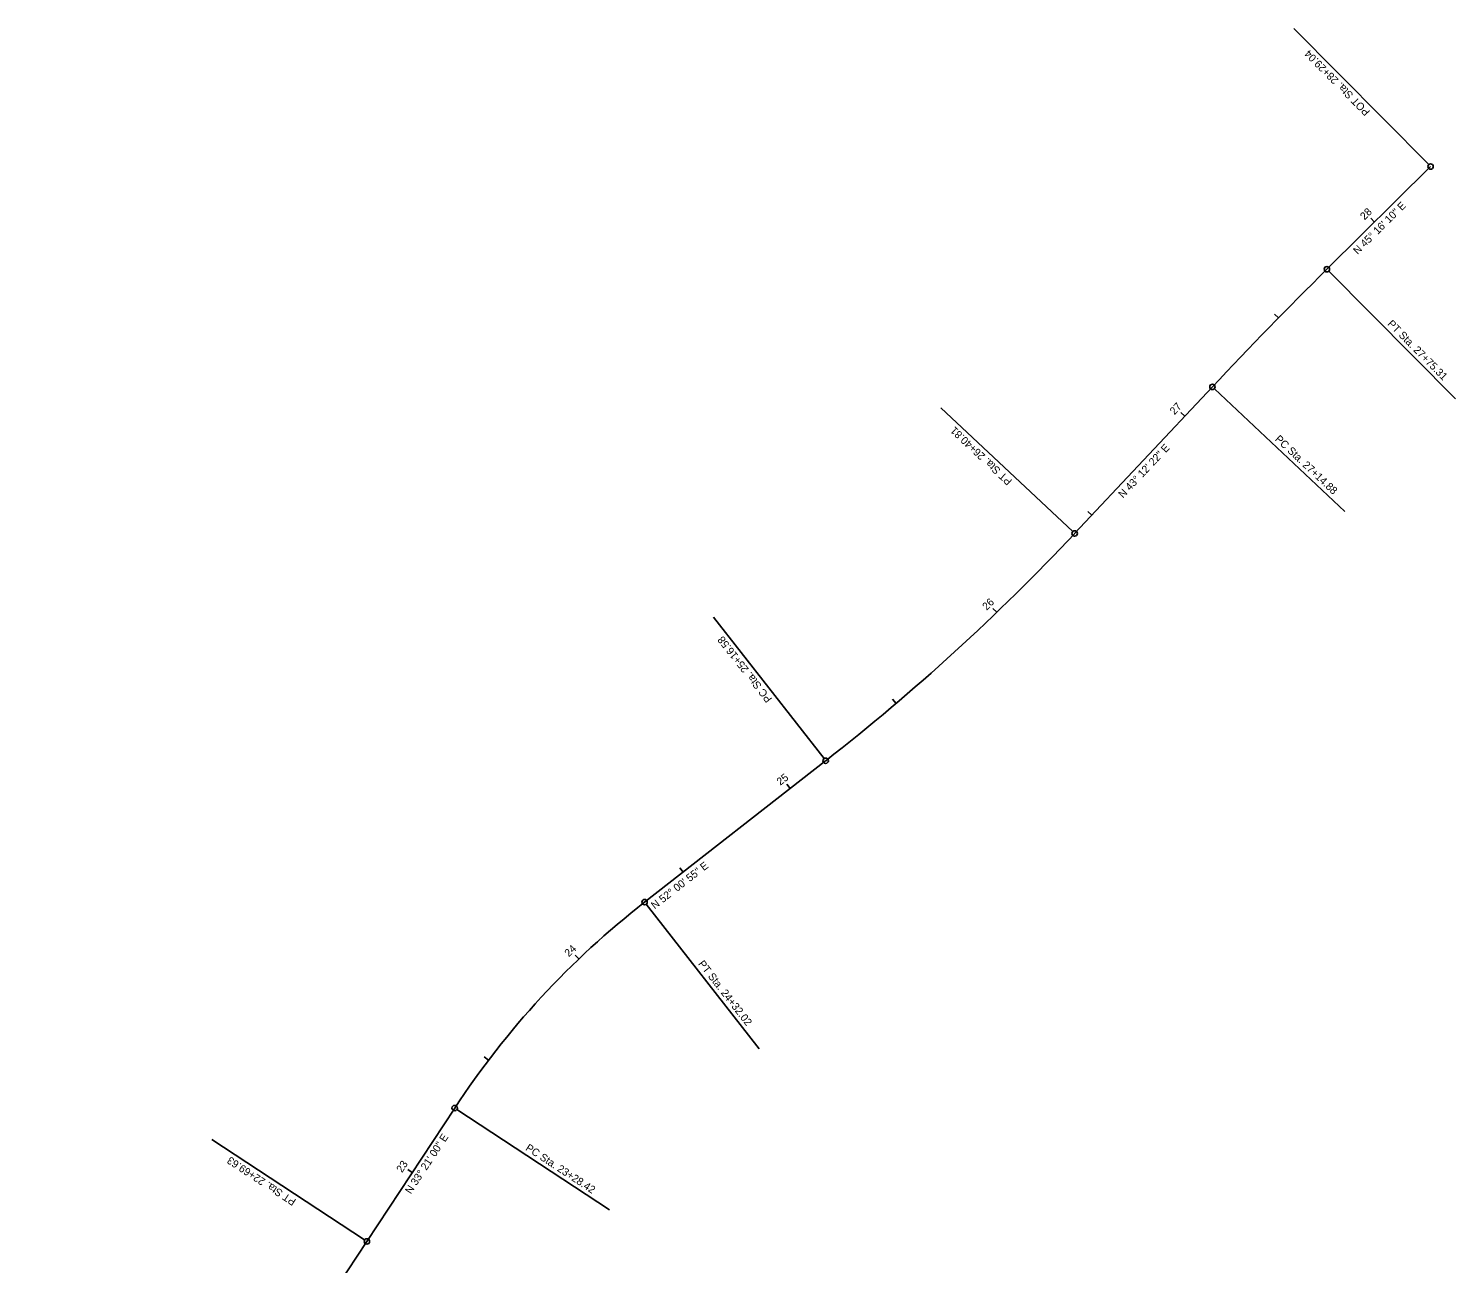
# Model space of a CAD drawing. Extents: x 1869622 to 1870464, y 422115 to 423925.
# Drawn here: x 1869717 to 1870243, y 423471 to 423925 of the extents above; entities that cross this region are included whole.
import ezdxf

# ---------------------------------------------------------------- set-up
doc = ezdxf.new("R2010")
doc.units = 0
doc.layers.add('GE_P_CL_20', color=7, linetype='Continuous')

msp = doc.modelspace()

# ---------------------------------------------------------------- linework, layer by layer
at = {"layer": 'GE_P_CL_20'}
for p, q in [((1870232.93, 423875.26), (1870183.3, 423925.36)), ((1870195.46, 423836.74), (1870233.63, 423874.55)), ((1870213, 423854.11), (1870211.59, 423855.53)), ((1870196.16, 423836.03), (1870242.78, 423788.97)), ((1870177.61, 423818.79), (1870176.18, 423820.19)), ((1870102.59, 423739.46), (1870153.3, 423793.44)), ((1870154.03, 423792.76), (1870202.11, 423747.6)), ((1870101.87, 423740.14), (1870053.31, 423785.75)), ((1870143.12, 423782.6), (1870141.66, 423783.97)), ((1870108.88, 423746.15), (1870107.43, 423747.52)), ((1870073.91, 423710.43), (1870072.53, 423711.87)), ((1870010.32, 423656.57), (1869969.68, 423708.61)), ((1870036.84, 423676.89), (1870035.54, 423678.42)), ((1869944.28, 423603.74), (1870010.93, 423655.79)), ((1869997.86, 423645.58), (1869996.63, 423647.16)), ((1869958.45, 423614.81), (1869957.22, 423616.38)), ((1869944.89, 423602.95), (1869986.44, 423549.75)), ((1869920.08, 423582.8), (1869918.69, 423584.24)), ((1869886.82, 423545.53), (1869885.23, 423546.74)), ((1869842.04, 423478.81), (1869874.36, 423527.92)), ((1869875.19, 423527.37), (1869931.3, 423490.45)), ((1869841.2, 423479.36), (1869784.93, 423516.4)), ((1869858.73, 423504.18), (1869857.06, 423505.28))]:
    msp.add_line(p, q, dxfattribs=at)
for centre in [(1870233.63, 423874.55), (1870195.46, 423836.74), (1870153.3, 423793.44), (1870102.59, 423739.46), (1870010.93, 423655.79), (1869944.28, 423603.74), (1869874.36, 423527.92), (1869842.04, 423478.81)]:
    msp.add_circle(centre, 1, dxfattribs=at)
for centre, radius, start, end in [((1871376.39, 422644.65), 1678, 134.73056, 136.79402), ((1869513.65, 424292.63), 808, 307.98484, 316.79402), ((1870139.99, 423353.1), 318, 127.9848, 146.6499), ((1868467.92, 424383.15), 1645, 319.42979, 326.64993)]:
    msp.add_arc(centre, radius, start, end, dxfattribs=at)

# ---------------------------------------------------------------- texts
for s, rotation, p in [('POT Sta. 28+29.04', 134.7306, (1870211.52, 423894.88)), ('N 45%%d 16\' 10" E', 44.7306, (1870206.75, 423842.01)), ('28', 44.7306, (1870209.32, 423854.69)), ('PT Sta. 27+75.31', 314.7306, (1870217.57, 423816.41)), ('27', 46.794, (1870139.34, 423782.96)), ('PT Sta. 26+40.81', 136.794, (1870079.77, 423758.97)), ('PC Sta. 27+14.88', 316.794, (1870176.13, 423773.92)), ('N 43%%d 12\' 22" E', 46.794, (1870120.41, 423752.29)), ('26', 43.9, (1870070.2, 423711.01)), ('PC Sta. 25+16.58', 127.9848, (1869991.36, 423678.57)), ('25', 37.9848, (1869994.23, 423646.55)), ('N 52%%d 00\' 55" E', 37.9848, (1869948.01, 423601.01)), ('24', 43.7538, (1869916.39, 423583.43)), ('PT Sta. 24+32.02', 307.9848, (1869963.85, 423580.96)), ('N 33%%d 21\' 00" E', 56.6499, (1869858.22, 423496.06)), ('PC Sta. 23+28.42', 326.6499, (1869900.19, 423512.6)), ('PT Sta. 22+69.63', 146.6499, (1869816.21, 423494.13)), ('23', 56.6499, (1869854.98, 423503.93))]:
    msp.add_text(s, height=2.8, rotation=rotation, dxfattribs=at).set_placement(p)

doc.saveas('drawing.dxf')
